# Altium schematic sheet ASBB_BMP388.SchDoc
size A4
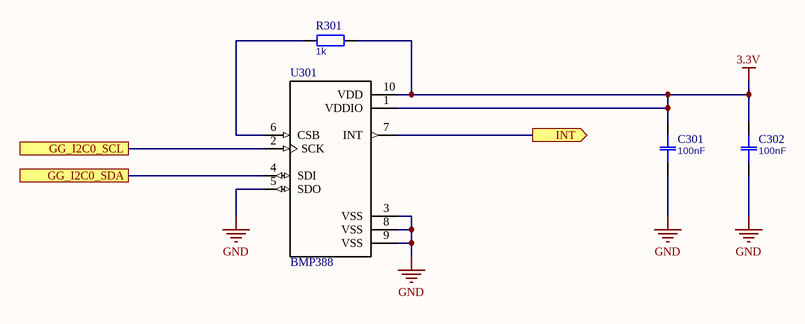
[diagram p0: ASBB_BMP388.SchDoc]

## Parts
C301  100nF  [0603]
C302  100nF  [0603]
R301  1k  [0603]
U301  BMP388  [PQFN50P200X200X80-10N]

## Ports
GG_I2C0_SCL, GG_I2C0_SDA, INT (out)

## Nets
3.3V: C301.2 C302.2 R301.2 U301.1(VDDIO) U301.10(VDD)
GND: C301.1 C302.1 U301.3(VSS) U301.5(SDO) U301.8(VSS) U301.9(VSS)
GG_I2C0_SCL: U301.2(SCK) ; port GG_I2C0_SCL
GG_I2C0_SDA: U301.4(SDI) ; port GG_I2C0_SDA
INT: U301.7(INT) ; port INT
NetR301_1: R301.1 U301.6(CSB)

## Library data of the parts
C301 C302 = Capacitor
R301 = Resistor
U301 = BMP388: P-Sensor SPI I2C 1, 25 Bar SMD; MF: Bosch Sensortec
